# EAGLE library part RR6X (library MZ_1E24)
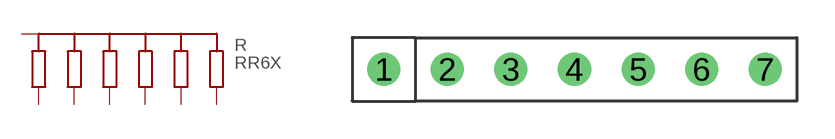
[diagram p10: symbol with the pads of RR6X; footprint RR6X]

Designator prefix R

## RR6X  [RR6X]
1  1  pas
2  2  pas
3  3  pas
4  4  pas
5  5  pas
6  6  pas
7  7  pas

## Footprint RR6X (pad centres in mm)
drill 0.813 round: 1 0,0; 2 2.54,0; 3 5.08,0; 4 7.62,0; 5 10.16,0; 6 12.7,0; 7 15.24,0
